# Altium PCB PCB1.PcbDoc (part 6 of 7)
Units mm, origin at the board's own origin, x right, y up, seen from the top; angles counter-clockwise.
Board outline 139.9 x 46.81 mm, 2 copper layers (Top Layer, Bottom Layer); 0 components, 100 nets, 100 pads, 0 vias.
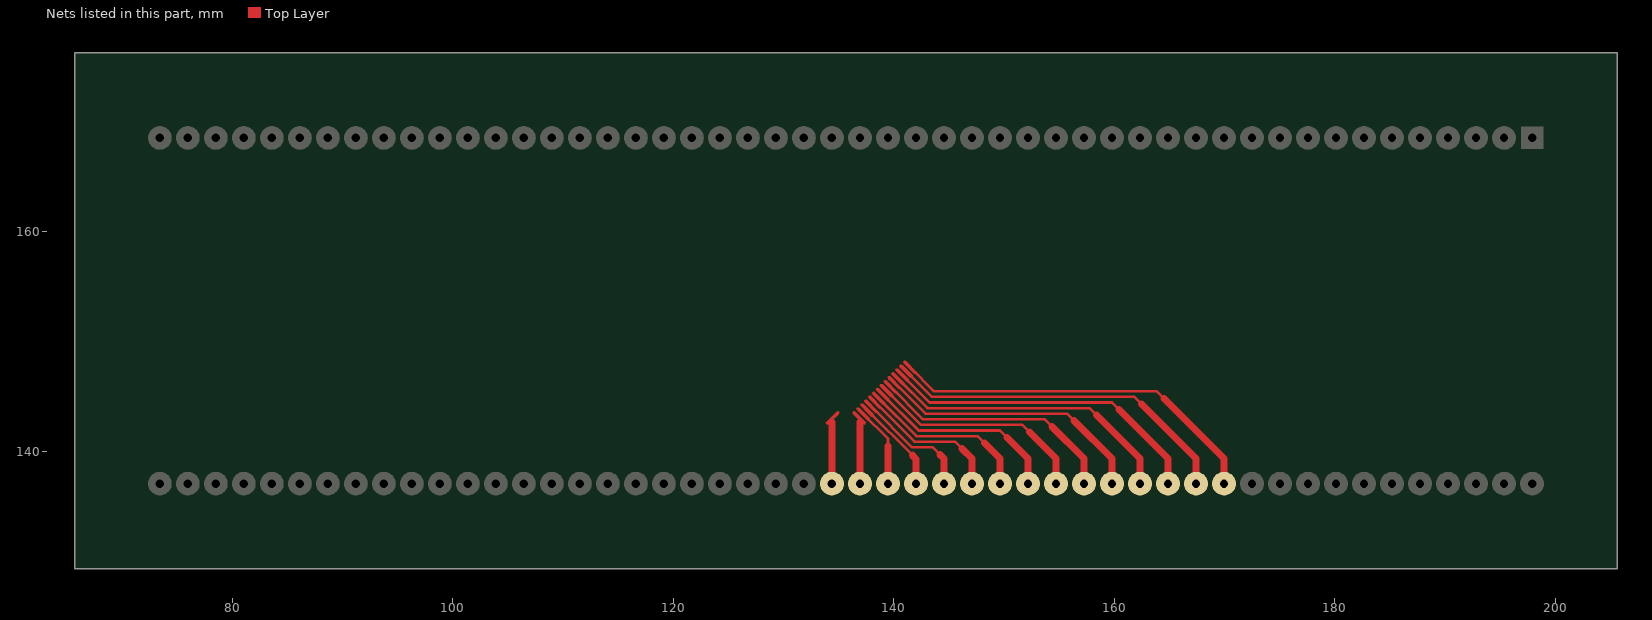
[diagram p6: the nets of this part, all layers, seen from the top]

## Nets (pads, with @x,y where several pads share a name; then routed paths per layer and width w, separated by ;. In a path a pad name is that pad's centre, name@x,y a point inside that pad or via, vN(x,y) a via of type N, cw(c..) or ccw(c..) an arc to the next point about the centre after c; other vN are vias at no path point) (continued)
$Net74: pad.1@134.387,137.086 | length 29.9
  Top Layer w0.03: 133.887,142.608 134.143,142.608 ; 133.887,142.623 134.158,142.623 ; 133.889,142.638 134.174,142.638 ; 133.892,142.592 134.128,142.592 ; 133.899,142.577 134.113,142.577 ; 133.91,142.562 134.098,142.562 ; 133.915,142.684 134.219,142.684 ; 133.922,142.547 134.082,142.547 ; 133.93,142.699 134.235,142.699 ; 133.938,142.532 134.067,142.532 ; 133.945,142.714 134.25,142.714 ; 133.96,142.516 134.049,142.516 ; 133.96,142.73 134.265,142.73 ; 133.976,142.745 134.28,142.745 ; 133.991,142.76 134.296,142.76 ; 134.006,142.775 134.311,142.775 ; 134.021,142.791 134.326,142.791 ; 134.037,142.806 134.341,142.806 ; 134.052,142.821 134.357,142.821 ; 134.067,142.836 134.372,142.836 ; 134.082,142.852 134.387,142.852 ; 134.098,142.867 134.402,142.867 ; 134.113,142.882 134.418,142.882 ; 134.128,142.897 134.433,142.897 ; 134.143,142.913 134.448,142.913 ; 134.158,142.928 134.463,142.928 ; 134.174,142.943 134.479,142.943 ; 134.189,142.653 133.892,142.653 ; 134.189,142.958 134.494,142.958 ; 134.204,142.669 133.899,142.669 ; 134.204,142.973 134.509,142.973 ; 134.219,142.989 134.527,142.989 ; 134.235,143.004 134.542,143.004 ; 134.25,143.019 134.557,143.019 ; 134.265,143.034 134.573,143.034 ; 134.28,143.05 134.588,143.05 ; 134.296,143.065 134.603,143.065 ; 134.311,143.08 134.618,143.08 ; 134.326,143.095 134.633,143.095 ; 134.341,143.111 134.649,143.111 ; 134.357,143.126 134.664,143.126 ; 134.372,143.141 134.679,143.141 ; 134.39,143.156 134.694,143.156 ; 134.405,143.172 134.71,143.172 ; 134.42,143.187 134.725,143.187 ; 134.435,143.202 134.74,143.202 ; 134.451,143.217 134.755,143.217 ; 134.466,143.233 134.771,143.233 ; 134.481,143.248 134.786,143.248 ; 134.496,143.263 134.801,143.263 ; 134.512,143.278 134.816,143.278 ; 134.527,143.294 134.832,143.294 ; 134.542,143.309 134.847,143.309 ; 134.557,143.324 134.862,143.324 ; 134.573,143.339 134.877,143.339 ; 134.588,143.354 134.893,143.354 ; 134.603,143.37 134.908,143.37 ; 134.618,143.385 134.923,143.385 ; 134.633,143.4 134.938,143.4 ; 134.649,143.415 134.954,143.415 ; 134.664,143.431 134.969,143.431 ; 134.679,143.446 134.984,143.446 ; 134.694,143.461 134.999,143.461 ; 134.71,143.476 135.009,143.476 ; 134.725,143.492 135.017,143.492 ; 134.74,143.507 135.02,143.507 ; 134.755,143.522 135.022,143.522 ; 134.771,143.537 135.02,143.537 ; 134.786,143.553 135.014,143.553 ; 134.801,143.568 135.004,143.568 ; 134.816,143.583 134.994,143.583 ; 134.832,143.598 134.979,143.598 ; 134.847,143.614 134.964,143.614 ; 134.867,143.629 134.941,143.629 ; 133.892,142.653 133.899,142.669 ; 133.892,142.653 133.884,142.62 133.887,142.603 133.892,142.587 133.912,142.557 133.94,142.529 133.971,142.509 133.986,142.504 134.004,142.501 134.037,142.509 134.049,142.516 ; 133.899,142.669 133.91,142.681 134.857,143.624 134.87,143.631 134.903,143.639 134.92,143.636 134.936,143.631 134.966,143.611 134.994,143.583 ; 134.049,142.516 134.997,143.459 135.007,143.471 135.014,143.487 135.022,143.52 135.02,143.537 ; 134.994,143.583 135.014,143.553 ; 135.014,143.553 135.02,143.537
  Top Layer w0.203: 134.387,142.674 134.387,143.001 134.453,143.07
  Top Layer w0.635: pad.1@134.387,137.086 134.387,142.674
$Net75: pad.1@136.927,137.086 | length 29.9
  Top Layer w0.03: 136.292,143.522 136.561,143.522 ; 136.295,143.507 136.577,143.507 ; 136.297,143.492 136.592,143.492 ; 136.305,143.476 136.607,143.476 ; 136.307,143.568 136.516,143.568 ; 136.317,143.461 136.622,143.461 ; 136.333,143.446 136.638,143.446 ; 136.333,143.598 136.485,143.598 ; 136.348,143.431 136.653,143.431 ; 136.351,143.614 136.47,143.614 ; 136.363,143.415 136.668,143.415 ; 136.373,143.629 136.447,143.629 ; 136.378,143.4 136.683,143.4 ; 136.394,143.385 136.698,143.385 ; 136.409,143.37 136.714,143.37 ; 136.424,143.354 136.729,143.354 ; 136.439,143.339 136.744,143.339 ; 136.455,143.324 136.759,143.324 ; 136.47,143.309 136.775,143.309 ; 136.485,143.294 136.79,143.294 ; 136.5,143.278 136.805,143.278 ; 136.5,143.583 136.317,143.583 ; 136.516,143.263 136.82,143.263 ; 136.531,143.248 136.836,143.248 ; 136.531,143.553 136.297,143.553 ; 136.546,143.233 136.851,143.233 ; 136.546,143.537 136.292,143.537 ; 136.561,143.217 136.866,143.217 ; 136.577,143.202 136.881,143.202 ; 136.592,143.187 136.897,143.187 ; 136.607,143.172 136.912,143.172 ; 136.622,143.156 136.927,143.156 ; 136.638,143.141 136.942,143.141 ; 136.653,143.126 136.955,143.126 ; 136.668,143.111 136.97,143.111 ; 136.683,143.095 136.986,143.095 ; 136.698,143.08 137.001,143.08 ; 136.714,143.065 137.016,143.065 ; 136.729,143.05 137.031,143.05 ; 136.744,143.034 137.046,143.034 ; 136.759,143.019 137.062,143.019 ; 136.775,143.004 137.077,143.004 ; 136.787,142.989 137.092,142.989 ; 136.803,142.973 137.107,142.973 ; 136.818,142.958 137.123,142.958 ; 136.833,142.943 137.138,142.943 ; 136.848,142.928 137.153,142.928 ; 136.864,142.913 137.168,142.913 ; 136.879,142.897 137.184,142.897 ; 136.894,142.882 137.199,142.882 ; 136.909,142.867 137.214,142.867 ; 136.925,142.852 137.229,142.852 ; 136.94,142.836 137.245,142.836 ; 136.955,142.821 137.26,142.821 ; 136.97,142.806 137.275,142.806 ; 136.986,142.791 137.29,142.791 ; 137.001,142.775 137.306,142.775 ; 137.016,142.76 137.321,142.76 ; 137.031,142.745 137.336,142.745 ; 137.046,142.73 137.351,142.73 ; 137.062,142.714 137.367,142.714 ; 137.077,142.699 137.382,142.699 ; 137.092,142.684 137.397,142.684 ; 137.107,142.669 137.412,142.669 ; 137.123,142.653 137.42,142.653 ; 137.138,142.638 137.425,142.638 ; 137.153,142.623 137.427,142.623 ; 137.168,142.608 137.427,142.608 ; 137.184,142.592 137.422,142.592 ; 137.199,142.577 137.415,142.577 ; 137.214,142.562 137.405,142.562 ; 137.229,142.547 137.389,142.547 ; 137.245,142.532 137.374,142.532 ; 137.354,142.516 137.26,142.516 ; 136.292,143.537 136.297,143.553 ; 136.292,143.537 136.29,143.52 136.297,143.487 136.305,143.474 137.247,142.526 137.26,142.516 ; 136.297,143.553 136.317,143.583 ; 136.317,143.583 136.345,143.611 136.376,143.631 136.391,143.636 136.409,143.639 136.442,143.631 136.457,143.624 136.47,143.614 ; 136.47,143.614 137.412,142.666 137.42,142.653 ; 137.26,142.516 137.275,142.509 137.308,142.501 137.326,142.504 137.341,142.509 137.372,142.529 137.4,142.557 137.42,142.587 137.425,142.603 137.427,142.62 137.42,142.653
  Top Layer w0.203: 136.859,143.07 136.927,143.001 136.927,142.674
  Top Layer w0.635: pad.1@136.927,137.086 136.927,142.674
$Net76: pad.1@139.467,137.086 | length 31.2
  Top Layer w0.03: 136.645,143.875 136.914,143.875 ; 136.648,143.86 136.93,143.86 ; 136.65,143.845 136.945,143.845 ; 136.658,143.829 136.96,143.829 ; 136.66,143.921 136.869,143.921 ; 136.671,143.814 136.975,143.814 ; 136.686,143.799 136.991,143.799 ; 136.686,143.951 136.838,143.951 ; 136.701,143.784 137.006,143.784 ; 136.704,143.967 136.823,143.967 ; 136.716,143.768 137.021,143.768 ; 136.726,143.982 136.8,143.982 ; 136.732,143.753 137.036,143.753 ; 136.747,143.738 137.052,143.738 ; 136.762,143.723 137.067,143.723 ; 136.777,143.708 137.082,143.708 ; 136.792,143.692 137.097,143.692 ; 136.808,143.677 137.113,143.677 ; 136.823,143.662 137.128,143.662 ; 136.838,143.647 137.143,143.647 ; 136.853,143.631 137.158,143.631 ; 136.853,143.936 136.671,143.936 ; 136.869,143.616 137.173,143.616 ; 136.884,143.601 137.189,143.601 ; 136.884,143.906 136.65,143.906 ; 136.899,143.586 137.204,143.586 ; 136.899,143.89 136.645,143.89 ; 136.914,143.57 137.219,143.57 ; 136.93,143.555 137.234,143.555 ; 136.945,143.54 137.25,143.54 ; 136.96,143.525 137.265,143.525 ; 136.975,143.509 137.28,143.509 ; 136.991,143.494 137.295,143.494 ; 137.006,143.479 137.308,143.479 ; 137.021,143.464 137.323,143.464 ; 137.036,143.448 137.339,143.448 ; 137.052,143.433 137.354,143.433 ; 137.067,143.418 137.369,143.418 ; 137.082,143.403 137.384,143.403 ; 137.097,143.387 137.4,143.387 ; 137.113,143.372 137.415,143.372 ; 137.128,143.357 137.43,143.357 ; 137.14,143.342 137.445,143.342 ; 137.156,143.327 137.46,143.327 ; 137.171,143.311 137.476,143.311 ; 137.186,143.296 137.491,143.296 ; 137.201,143.281 137.506,143.281 ; 137.217,143.266 137.521,143.266 ; 137.232,143.25 137.537,143.25 ; 137.247,143.235 137.552,143.235 ; 137.262,143.22 137.567,143.22 ; 137.278,143.205 137.582,143.205 ; 137.293,143.189 137.598,143.189 ; 137.308,143.174 137.613,143.174 ; 137.323,143.159 137.628,143.159 ; 137.339,143.144 137.643,143.144 ; 137.354,143.128 137.659,143.128 ; 137.369,143.113 137.674,143.113 ; 137.384,143.098 137.689,143.098 ; 137.4,143.083 137.704,143.083 ; 137.415,143.067 137.72,143.067 ; 137.43,143.052 137.735,143.052 ; 137.445,143.037 137.75,143.037 ; 137.46,143.022 137.765,143.022 ; 137.476,143.006 137.773,143.006 ; 137.491,142.991 137.778,142.991 ; 137.506,142.976 137.781,142.976 ; 137.521,142.961 137.781,142.961 ; 137.537,142.946 137.775,142.946 ; 137.552,142.93 137.768,142.93 ; 137.567,142.915 137.758,142.915 ; 137.582,142.9 137.742,142.9 ; 137.598,142.885 137.727,142.885 ; 137.707,142.869 137.613,142.869 ; 136.645,143.89 136.65,143.906 ; 136.645,143.89 136.643,143.873 136.65,143.84 136.658,143.827 137.6,142.879 137.613,142.869 ; 136.65,143.906 136.671,143.936 ; 136.671,143.936 136.698,143.964 136.729,143.984 136.744,143.989 136.762,143.992 136.795,143.984 136.81,143.977 136.823,143.967 ; 136.823,143.967 137.765,143.019 137.773,143.006 ; 137.613,142.869 137.628,142.862 137.661,142.854 137.679,142.857 137.694,142.862 137.725,142.882 137.753,142.91 137.773,142.94 137.778,142.956 137.781,142.973 137.773,143.006
  Top Layer w0.241: 137.212,143.423 139.467,141.168 139.467,140.515
  Top Layer w0.635: pad.1@139.467,137.086 139.467,140.515
$Net77: pad.1@142.007,137.086 | length 32.4
  Top Layer w0.03: 136.998,144.228 137.267,144.228 ; 137.001,144.213 137.283,144.213 ; 137.003,144.198 137.298,144.198 ; 137.011,144.183 137.313,144.183 ; 137.013,144.274 137.222,144.274 ; 137.024,144.167 137.328,144.167 ; 137.039,144.152 137.344,144.152 ; 137.039,144.304 137.191,144.304 ; 137.054,144.137 137.359,144.137 ; 137.057,144.32 137.176,144.32 ; 137.069,144.122 137.374,144.122 ; 137.079,144.335 137.153,144.335 ; 137.085,144.106 137.389,144.106 ; 137.1,144.091 137.405,144.091 ; 137.115,144.076 137.42,144.076 ; 137.13,144.061 137.435,144.061 ; 137.146,144.045 137.45,144.045 ; 137.161,144.03 137.466,144.03 ; 137.176,144.015 137.481,144.015 ; 137.191,144 137.496,144 ; 137.206,143.984 137.511,143.984 ; 137.206,144.289 137.024,144.289 ; 137.222,143.969 137.527,143.969 ; 137.237,143.954 137.542,143.954 ; 137.237,144.259 137.003,144.259 ; 137.252,143.939 137.557,143.939 ; 137.252,144.243 136.998,144.243 ; 137.267,143.923 137.572,143.923 ; 137.283,143.908 137.587,143.908 ; 137.298,143.893 137.603,143.893 ; 137.313,143.878 137.618,143.878 ; 137.328,143.862 137.633,143.862 ; 137.344,143.847 137.648,143.847 ; 137.359,143.832 137.661,143.832 ; 137.374,143.817 137.676,143.817 ; 137.389,143.802 137.692,143.802 ; 137.405,143.786 137.707,143.786 ; 137.42,143.771 137.722,143.771 ; 137.435,143.756 137.737,143.756 ; 137.45,143.741 137.753,143.741 ; 137.466,143.725 137.768,143.725 ; 137.481,143.71 137.783,143.71 ; 137.494,143.695 137.798,143.695 ; 137.509,143.68 137.814,143.68 ; 137.524,143.664 137.829,143.664 ; 137.539,143.649 137.844,143.649 ; 137.554,143.634 137.859,143.634 ; 137.57,143.619 137.875,143.619 ; 137.585,143.603 137.89,143.603 ; 137.6,143.588 137.905,143.588 ; 137.615,143.573 137.92,143.573 ; 137.631,143.558 137.935,143.558 ; 137.646,143.542 137.951,143.542 ; 137.661,143.527 137.966,143.527 ; 137.676,143.512 137.981,143.512 ; 137.692,143.497 137.996,143.497 ; 137.707,143.481 138.012,143.481 ; 137.722,143.466 138.027,143.466 ; 137.737,143.451 138.042,143.451 ; 137.753,143.436 138.057,143.436 ; 137.768,143.421 138.073,143.421 ; 137.783,143.405 138.088,143.405 ; 137.798,143.39 138.103,143.39 ; 137.814,143.375 138.118,143.375 ; 137.829,143.36 138.126,143.36 ; 137.844,143.344 138.131,143.344 ; 137.859,143.329 138.134,143.329 ; 137.875,143.314 138.134,143.314 ; 137.89,143.299 138.129,143.299 ; 137.905,143.283 138.121,143.283 ; 137.92,143.268 138.111,143.268 ; 137.935,143.253 138.095,143.253 ; 137.951,143.238 138.08,143.238 ; 138.06,143.222 137.966,143.222 ; 136.998,144.243 137.003,144.259 ; 136.998,144.243 136.996,144.226 137.003,144.193 137.011,144.18 137.953,143.233 137.966,143.222 ; 137.003,144.259 137.024,144.289 ; 137.024,144.289 137.052,144.317 137.082,144.337 137.097,144.343 137.115,144.345 137.148,144.337 137.163,144.33 137.176,144.32 ; 137.176,144.32 138.118,143.372 138.126,143.36 ; 137.966,143.222 137.981,143.215 138.014,143.207 138.032,143.21 138.047,143.215 138.078,143.235 138.106,143.263 138.126,143.294 138.131,143.309 138.134,143.327 138.126,143.36
  Top Layer w0.241: 137.565,143.776 141.672,139.671
  Top Layer w0.635: 141.672,139.671 142.007,139.336 pad.1@142.007,137.086
$Net78: pad.1@144.547,137.086 | length 34.8
  Top Layer w0.03: 137.351,144.581 137.621,144.581 ; 137.354,144.566 137.636,144.566 ; 137.356,144.551 137.651,144.551 ; 137.364,144.536 137.666,144.536 ; 137.367,144.627 137.575,144.627 ; 137.377,144.52 137.681,144.52 ; 137.392,144.505 137.697,144.505 ; 137.392,144.657 137.544,144.657 ; 137.407,144.49 137.712,144.49 ; 137.41,144.673 137.529,144.673 ; 137.422,144.475 137.727,144.475 ; 137.433,144.688 137.506,144.688 ; 137.438,144.459 137.742,144.459 ; 137.453,144.444 137.758,144.444 ; 137.468,144.429 137.773,144.429 ; 137.483,144.414 137.788,144.414 ; 137.499,144.398 137.803,144.398 ; 137.514,144.383 137.819,144.383 ; 137.529,144.368 137.834,144.368 ; 137.544,144.353 137.849,144.353 ; 137.56,144.337 137.864,144.337 ; 137.56,144.642 137.377,144.642 ; 137.575,144.322 137.88,144.322 ; 137.59,144.307 137.895,144.307 ; 137.59,144.612 137.356,144.612 ; 137.605,144.292 137.91,144.292 ; 137.605,144.597 137.351,144.597 ; 137.621,144.276 137.925,144.276 ; 137.636,144.261 137.941,144.261 ; 137.651,144.246 137.956,144.246 ; 137.666,144.231 137.971,144.231 ; 137.681,144.216 137.986,144.216 ; 137.697,144.2 138.002,144.2 ; 137.712,144.185 138.014,144.185 ; 137.727,144.17 138.029,144.17 ; 137.742,144.155 138.045,144.155 ; 137.758,144.139 138.06,144.139 ; 137.773,144.124 138.075,144.124 ; 137.788,144.109 138.09,144.109 ; 137.803,144.094 138.106,144.094 ; 137.819,144.078 138.121,144.078 ; 137.834,144.063 138.136,144.063 ; 137.847,144.048 138.151,144.048 ; 137.862,144.033 138.167,144.033 ; 137.877,144.017 138.182,144.017 ; 137.892,144.002 138.197,144.002 ; 137.908,143.987 138.212,143.987 ; 137.923,143.972 138.228,143.972 ; 137.938,143.956 138.243,143.956 ; 137.953,143.941 138.258,143.941 ; 137.968,143.926 138.273,143.926 ; 137.984,143.911 138.289,143.911 ; 137.999,143.895 138.304,143.895 ; 138.014,143.88 138.319,143.88 ; 138.029,143.865 138.334,143.865 ; 138.045,143.85 138.349,143.85 ; 138.06,143.835 138.365,143.835 ; 138.075,143.819 138.38,143.819 ; 138.09,143.804 138.395,143.804 ; 138.106,143.789 138.41,143.789 ; 138.121,143.774 138.426,143.774 ; 138.136,143.758 138.441,143.758 ; 138.151,143.743 138.456,143.743 ; 138.167,143.728 138.471,143.728 ; 138.182,143.713 138.479,143.713 ; 138.197,143.697 138.484,143.697 ; 138.212,143.682 138.487,143.682 ; 138.228,143.667 138.487,143.667 ; 138.243,143.652 138.482,143.652 ; 138.258,143.636 138.474,143.636 ; 138.273,143.621 138.464,143.621 ; 138.289,143.606 138.449,143.606 ; 138.304,143.591 138.433,143.591 ; 138.413,143.575 138.319,143.575 ; 137.351,144.597 137.356,144.612 ; 137.351,144.597 137.349,144.579 137.356,144.546 137.364,144.533 138.306,143.586 138.319,143.575 ; 137.356,144.612 137.377,144.642 ; 137.377,144.642 137.405,144.67 137.435,144.691 137.45,144.696 137.468,144.698 137.501,144.691 137.516,144.683 137.529,144.673 ; 137.529,144.673 138.471,143.725 138.479,143.713 ; 138.319,143.575 138.334,143.568 138.367,143.56 138.385,143.563 138.4,143.568 138.431,143.588 138.459,143.616 138.479,143.647 138.484,143.662 138.487,143.68 138.479,143.713
  Top Layer w0.241: 137.918,144.129 141.662,140.388 143.531,140.388 144.166,139.753
  Top Layer w0.635: 144.166,139.753 144.547,139.372 pad.1@144.547,137.086
$Net79: pad.1@147.087,137.086 | length 37.1
  Top Layer w0.03: 137.707,144.937 137.976,144.937 ; 137.709,144.922 137.991,144.922 ; 137.712,144.906 138.007,144.906 ; 137.72,144.891 138.022,144.891 ; 137.722,144.983 137.93,144.983 ; 137.732,144.876 138.037,144.876 ; 137.748,144.861 138.052,144.861 ; 137.748,145.013 137.9,145.013 ; 137.763,144.845 138.068,144.845 ; 137.765,145.028 137.885,145.028 ; 137.778,144.83 138.083,144.83 ; 137.788,145.044 137.862,145.044 ; 137.793,144.815 138.098,144.815 ; 137.808,144.8 138.113,144.8 ; 137.824,144.784 138.129,144.784 ; 137.839,144.769 138.144,144.769 ; 137.854,144.754 138.159,144.754 ; 137.869,144.739 138.174,144.739 ; 137.885,144.724 138.189,144.724 ; 137.9,144.708 138.205,144.708 ; 137.915,144.693 138.22,144.693 ; 137.915,144.998 137.732,144.998 ; 137.93,144.678 138.235,144.678 ; 137.946,144.663 138.25,144.663 ; 137.946,144.967 137.712,144.967 ; 137.961,144.647 138.266,144.647 ; 137.961,144.952 137.707,144.952 ; 137.976,144.632 138.281,144.632 ; 137.991,144.617 138.296,144.617 ; 138.007,144.602 138.311,144.602 ; 138.022,144.586 138.327,144.586 ; 138.037,144.571 138.342,144.571 ; 138.052,144.556 138.357,144.556 ; 138.068,144.541 138.37,144.541 ; 138.083,144.525 138.385,144.525 ; 138.098,144.51 138.4,144.51 ; 138.113,144.495 138.416,144.495 ; 138.129,144.48 138.431,144.48 ; 138.144,144.464 138.446,144.464 ; 138.159,144.449 138.461,144.449 ; 138.174,144.434 138.476,144.434 ; 138.189,144.419 138.492,144.419 ; 138.202,144.403 138.507,144.403 ; 138.217,144.388 138.522,144.388 ; 138.233,144.373 138.537,144.373 ; 138.248,144.358 138.553,144.358 ; 138.263,144.343 138.568,144.343 ; 138.278,144.327 138.583,144.327 ; 138.294,144.312 138.598,144.312 ; 138.309,144.297 138.614,144.297 ; 138.324,144.282 138.629,144.282 ; 138.339,144.266 138.644,144.266 ; 138.355,144.251 138.659,144.251 ; 138.37,144.236 138.675,144.236 ; 138.385,144.221 138.69,144.221 ; 138.4,144.205 138.705,144.205 ; 138.416,144.19 138.72,144.19 ; 138.431,144.175 138.736,144.175 ; 138.446,144.16 138.751,144.16 ; 138.461,144.144 138.766,144.144 ; 138.476,144.129 138.781,144.129 ; 138.492,144.114 138.797,144.114 ; 138.507,144.099 138.812,144.099 ; 138.522,144.083 138.827,144.083 ; 138.537,144.068 138.835,144.068 ; 138.553,144.053 138.84,144.053 ; 138.568,144.038 138.842,144.038 ; 138.583,144.022 138.842,144.022 ; 138.598,144.007 138.837,144.007 ; 138.614,143.992 138.83,143.992 ; 138.629,143.977 138.819,143.977 ; 138.644,143.962 138.804,143.962 ; 138.659,143.946 138.789,143.946 ; 138.769,143.931 138.675,143.931 ; 137.707,144.952 137.712,144.967 ; 137.707,144.952 137.704,144.934 137.712,144.901 137.72,144.889 138.662,143.941 138.675,143.931 ; 137.712,144.967 137.732,144.998 ; 137.732,144.998 137.76,145.026 137.791,145.046 137.806,145.051 137.824,145.054 137.857,145.046 137.872,145.038 137.885,145.028 ; 137.885,145.028 138.827,144.081 138.835,144.068 ; 138.675,143.931 138.69,143.923 138.723,143.916 138.741,143.918 138.756,143.923 138.786,143.944 138.814,143.972 138.835,144.002 138.84,144.017 138.842,144.035 138.835,144.068
  Top Layer w0.241: 138.273,144.485 141.86,140.896 145.563,140.896 146.198,140.261
  Top Layer w0.635: 146.198,140.261 147.087,139.372 pad.1@147.087,137.086
$Net80: pad.1@149.627,137.086 | length 39.5
  Top Layer w0.03: 138.06,145.29 138.329,145.29 ; 138.062,145.275 138.344,145.275 ; 138.065,145.259 138.36,145.259 ; 138.073,145.244 138.375,145.244 ; 138.075,145.336 138.283,145.336 ; 138.085,145.229 138.39,145.229 ; 138.101,145.214 138.405,145.214 ; 138.101,145.366 138.253,145.366 ; 138.116,145.199 138.421,145.199 ; 138.118,145.381 138.238,145.381 ; 138.131,145.183 138.436,145.183 ; 138.141,145.397 138.215,145.397 ; 138.146,145.168 138.451,145.168 ; 138.162,145.153 138.466,145.153 ; 138.177,145.138 138.482,145.138 ; 138.192,145.122 138.497,145.122 ; 138.207,145.107 138.512,145.107 ; 138.222,145.092 138.527,145.092 ; 138.238,145.077 138.543,145.077 ; 138.253,145.061 138.558,145.061 ; 138.268,145.046 138.573,145.046 ; 138.268,145.351 138.085,145.351 ; 138.283,145.031 138.588,145.031 ; 138.299,145.016 138.603,145.016 ; 138.299,145.32 138.065,145.32 ; 138.314,145 138.619,145 ; 138.314,145.305 138.06,145.305 ; 138.329,144.985 138.634,144.985 ; 138.344,144.97 138.649,144.97 ; 138.36,144.955 138.664,144.955 ; 138.375,144.939 138.68,144.939 ; 138.39,144.924 138.695,144.924 ; 138.405,144.909 138.71,144.909 ; 138.421,144.894 138.723,144.894 ; 138.436,144.878 138.738,144.878 ; 138.451,144.863 138.753,144.863 ; 138.466,144.848 138.769,144.848 ; 138.482,144.833 138.784,144.833 ; 138.497,144.818 138.799,144.818 ; 138.512,144.802 138.814,144.802 ; 138.527,144.787 138.83,144.787 ; 138.543,144.772 138.845,144.772 ; 138.555,144.757 138.86,144.757 ; 138.57,144.741 138.875,144.741 ; 138.586,144.726 138.891,144.726 ; 138.601,144.711 138.906,144.711 ; 138.616,144.696 138.921,144.696 ; 138.631,144.68 138.936,144.68 ; 138.647,144.665 138.951,144.665 ; 138.662,144.65 138.967,144.65 ; 138.677,144.635 138.982,144.635 ; 138.692,144.619 138.997,144.619 ; 138.708,144.604 139.012,144.604 ; 138.723,144.589 139.028,144.589 ; 138.738,144.574 139.043,144.574 ; 138.753,144.558 139.058,144.558 ; 138.769,144.543 139.073,144.543 ; 138.784,144.528 139.089,144.528 ; 138.799,144.513 139.104,144.513 ; 138.814,144.497 139.119,144.497 ; 138.83,144.482 139.134,144.482 ; 138.845,144.467 139.15,144.467 ; 138.86,144.452 139.165,144.452 ; 138.875,144.437 139.18,144.437 ; 138.891,144.421 139.188,144.421 ; 138.906,144.406 139.193,144.406 ; 138.921,144.391 139.195,144.391 ; 138.936,144.376 139.195,144.376 ; 138.951,144.36 139.19,144.36 ; 138.967,144.345 139.183,144.345 ; 138.982,144.33 139.172,144.33 ; 138.997,144.315 139.157,144.315 ; 139.012,144.299 139.142,144.299 ; 139.122,144.284 139.028,144.284 ; 138.06,145.305 138.065,145.32 ; 138.06,145.305 138.057,145.287 138.065,145.254 138.073,145.242 139.015,144.294 139.028,144.284 ; 138.065,145.32 138.085,145.351 ; 138.085,145.351 138.113,145.379 138.144,145.399 138.159,145.404 138.177,145.407 138.21,145.399 138.225,145.392 138.238,145.381 ; 138.238,145.381 139.18,144.434 139.188,144.421 ; 139.028,144.284 139.043,144.276 139.076,144.269 139.094,144.271 139.109,144.276 139.139,144.297 139.167,144.325 139.188,144.355 139.193,144.37 139.195,144.388 139.188,144.421
  Top Layer w0.241: 138.626,144.838 142.06,141.404 147.595,141.404 148.23,140.769
  Top Layer w0.635: 148.23,140.769 149.627,139.372 pad.1@149.627,137.086
$Net81: pad.1@152.167,137.086 | length 41.8
  Top Layer w0.03: 138.413,145.643 138.682,145.643 ; 138.416,145.628 138.697,145.628 ; 138.418,145.613 138.713,145.613 ; 138.426,145.597 138.728,145.597 ; 138.428,145.689 138.637,145.689 ; 138.438,145.582 138.743,145.582 ; 138.454,145.567 138.758,145.567 ; 138.454,145.719 138.606,145.719 ; 138.469,145.552 138.774,145.552 ; 138.471,145.734 138.591,145.734 ; 138.484,145.536 138.789,145.536 ; 138.494,145.75 138.568,145.75 ; 138.499,145.521 138.804,145.521 ; 138.515,145.506 138.819,145.506 ; 138.53,145.491 138.835,145.491 ; 138.545,145.475 138.85,145.475 ; 138.56,145.46 138.865,145.46 ; 138.576,145.445 138.88,145.445 ; 138.591,145.43 138.896,145.43 ; 138.606,145.414 138.911,145.414 ; 138.621,145.399 138.926,145.399 ; 138.621,145.704 138.438,145.704 ; 138.637,145.384 138.941,145.384 ; 138.652,145.369 138.957,145.369 ; 138.652,145.673 138.418,145.673 ; 138.667,145.353 138.972,145.353 ; 138.667,145.658 138.413,145.658 ; 138.682,145.338 138.987,145.338 ; 138.697,145.323 139.002,145.323 ; 138.713,145.308 139.018,145.308 ; 138.728,145.292 139.033,145.292 ; 138.743,145.277 139.048,145.277 ; 138.758,145.262 139.063,145.262 ; 138.774,145.247 139.076,145.247 ; 138.789,145.232 139.091,145.232 ; 138.804,145.216 139.106,145.216 ; 138.819,145.201 139.122,145.201 ; 138.835,145.186 139.137,145.186 ; 138.85,145.171 139.152,145.171 ; 138.865,145.155 139.167,145.155 ; 138.88,145.14 139.183,145.14 ; 138.896,145.125 139.198,145.125 ; 138.908,145.11 139.213,145.11 ; 138.924,145.094 139.228,145.094 ; 138.939,145.079 139.244,145.079 ; 138.954,145.064 139.259,145.064 ; 138.969,145.049 139.274,145.049 ; 138.984,145.033 139.289,145.033 ; 139,145.018 139.305,145.018 ; 139.015,145.003 139.32,145.003 ; 139.03,144.988 139.335,144.988 ; 139.045,144.972 139.35,144.972 ; 139.061,144.957 139.365,144.957 ; 139.076,144.942 139.381,144.942 ; 139.091,144.927 139.396,144.927 ; 139.106,144.911 139.411,144.911 ; 139.122,144.896 139.426,144.896 ; 139.137,144.881 139.442,144.881 ; 139.152,144.866 139.457,144.866 ; 139.167,144.851 139.472,144.851 ; 139.183,144.835 139.487,144.835 ; 139.198,144.82 139.503,144.82 ; 139.213,144.805 139.518,144.805 ; 139.228,144.79 139.533,144.79 ; 139.244,144.774 139.541,144.774 ; 139.259,144.759 139.546,144.759 ; 139.274,144.744 139.548,144.744 ; 139.289,144.729 139.548,144.729 ; 139.305,144.713 139.543,144.713 ; 139.32,144.698 139.536,144.698 ; 139.335,144.683 139.526,144.683 ; 139.35,144.668 139.51,144.668 ; 139.365,144.652 139.495,144.652 ; 139.475,144.637 139.381,144.637 ; 138.413,145.658 138.418,145.673 ; 138.413,145.658 138.41,145.64 138.418,145.607 138.426,145.595 139.368,144.647 139.381,144.637 ; 138.418,145.673 138.438,145.704 ; 138.438,145.704 138.466,145.732 138.497,145.752 138.512,145.757 138.53,145.76 138.563,145.752 138.578,145.745 138.591,145.734 ; 138.591,145.734 139.533,144.787 139.541,144.774 ; 139.381,144.637 139.396,144.63 139.429,144.622 139.447,144.624 139.462,144.63 139.492,144.65 139.52,144.678 139.541,144.708 139.546,144.724 139.548,144.741 139.541,144.774
  Top Layer w0.241: 138.979,145.191 142.259,141.912 149.627,141.912 150.262,141.277
  Top Layer w0.635: 150.262,141.277 152.167,139.372 pad.1@152.167,137.086
$Net82: pad.1@154.707,137.086 | length 44.1
  Top Layer w0.03: 138.766,145.996 139.035,145.996 ; 138.769,145.981 139.051,145.981 ; 138.771,145.966 139.066,145.966 ; 138.779,145.95 139.081,145.95 ; 138.781,146.042 138.99,146.042 ; 138.791,145.935 139.096,145.935 ; 138.807,145.92 139.111,145.92 ; 138.807,146.072 138.959,146.072 ; 138.822,145.905 139.127,145.905 ; 138.824,146.088 138.944,146.088 ; 138.837,145.889 139.142,145.889 ; 138.847,146.103 138.921,146.103 ; 138.852,145.874 139.157,145.874 ; 138.868,145.859 139.172,145.859 ; 138.883,145.844 139.188,145.844 ; 138.898,145.828 139.203,145.828 ; 138.913,145.813 139.218,145.813 ; 138.929,145.798 139.233,145.798 ; 138.944,145.783 139.249,145.783 ; 138.959,145.767 139.264,145.767 ; 138.974,145.752 139.279,145.752 ; 138.974,146.057 138.791,146.057 ; 138.99,145.737 139.294,145.737 ; 139.005,145.722 139.31,145.722 ; 139.005,146.027 138.771,146.027 ; 139.02,145.707 139.325,145.707 ; 139.02,146.011 138.766,146.011 ; 139.035,145.691 139.34,145.691 ; 139.051,145.676 139.355,145.676 ; 139.066,145.661 139.371,145.661 ; 139.081,145.646 139.386,145.646 ; 139.096,145.63 139.401,145.63 ; 139.111,145.615 139.416,145.615 ; 139.127,145.6 139.429,145.6 ; 139.142,145.585 139.444,145.585 ; 139.157,145.569 139.459,145.569 ; 139.172,145.554 139.475,145.554 ; 139.188,145.539 139.49,145.539 ; 139.203,145.524 139.505,145.524 ; 139.218,145.508 139.52,145.508 ; 139.233,145.493 139.536,145.493 ; 139.249,145.478 139.551,145.478 ; 139.261,145.463 139.566,145.463 ; 139.277,145.447 139.581,145.447 ; 139.292,145.432 139.597,145.432 ; 139.307,145.417 139.612,145.417 ; 139.322,145.402 139.627,145.402 ; 139.338,145.386 139.642,145.386 ; 139.353,145.371 139.658,145.371 ; 139.368,145.356 139.673,145.356 ; 139.383,145.341 139.688,145.341 ; 139.399,145.326 139.703,145.326 ; 139.414,145.31 139.719,145.31 ; 139.429,145.295 139.734,145.295 ; 139.444,145.28 139.749,145.28 ; 139.459,145.265 139.764,145.265 ; 139.475,145.249 139.78,145.249 ; 139.49,145.234 139.795,145.234 ; 139.505,145.219 139.81,145.219 ; 139.52,145.204 139.825,145.204 ; 139.536,145.188 139.84,145.188 ; 139.551,145.173 139.856,145.173 ; 139.566,145.158 139.871,145.158 ; 139.581,145.143 139.886,145.143 ; 139.597,145.127 139.894,145.127 ; 139.612,145.112 139.899,145.112 ; 139.627,145.097 139.901,145.097 ; 139.642,145.082 139.901,145.082 ; 139.658,145.066 139.896,145.066 ; 139.673,145.051 139.889,145.051 ; 139.688,145.036 139.879,145.036 ; 139.703,145.021 139.863,145.021 ; 139.719,145.005 139.848,145.005 ; 139.828,144.99 139.734,144.99 ; 138.766,146.011 138.771,146.027 ; 138.766,146.011 138.764,145.994 138.771,145.961 138.779,145.948 139.721,145 139.734,144.99 ; 138.771,146.027 138.791,146.057 ; 138.791,146.057 138.819,146.085 138.85,146.105 138.865,146.11 138.883,146.113 138.916,146.105 138.931,146.098 138.944,146.088 ; 138.944,146.088 139.886,145.14 139.894,145.127 ; 139.734,144.99 139.749,144.983 139.782,144.975 139.8,144.978 139.815,144.983 139.846,145.003 139.873,145.031 139.894,145.061 139.899,145.077 139.901,145.094 139.894,145.127
  Top Layer w0.241: 139.332,145.544 142.459,142.42 151.659,142.42 152.294,141.785
  Top Layer w0.635: 152.294,141.785 154.707,139.372 pad.1@154.707,137.086
$Net83: pad.1@157.247,137.086 | length 46.5
  Top Layer w0.03: 139.119,146.349 139.388,146.349 ; 139.122,146.334 139.404,146.334 ; 139.124,146.319 139.419,146.319 ; 139.132,146.303 139.434,146.303 ; 139.134,146.395 139.343,146.395 ; 139.145,146.288 139.449,146.288 ; 139.16,146.273 139.465,146.273 ; 139.16,146.425 139.312,146.425 ; 139.175,146.258 139.48,146.258 ; 139.178,146.441 139.297,146.441 ; 139.19,146.242 139.495,146.242 ; 139.2,146.456 139.274,146.456 ; 139.205,146.227 139.51,146.227 ; 139.221,146.212 139.526,146.212 ; 139.236,146.197 139.541,146.197 ; 139.251,146.181 139.556,146.181 ; 139.266,146.166 139.571,146.166 ; 139.282,146.151 139.586,146.151 ; 139.297,146.136 139.602,146.136 ; 139.312,146.121 139.617,146.121 ; 139.327,146.105 139.632,146.105 ; 139.327,146.41 139.145,146.41 ; 139.343,146.09 139.647,146.09 ; 139.358,146.075 139.663,146.075 ; 139.358,146.38 139.124,146.38 ; 139.373,146.06 139.678,146.06 ; 139.373,146.364 139.119,146.364 ; 139.388,146.044 139.693,146.044 ; 139.404,146.029 139.708,146.029 ; 139.419,146.014 139.724,146.014 ; 139.434,145.999 139.739,145.999 ; 139.449,145.983 139.754,145.983 ; 139.465,145.968 139.769,145.968 ; 139.48,145.953 139.782,145.953 ; 139.495,145.938 139.797,145.938 ; 139.51,145.922 139.813,145.922 ; 139.526,145.907 139.828,145.907 ; 139.541,145.892 139.843,145.892 ; 139.556,145.877 139.858,145.877 ; 139.571,145.861 139.873,145.861 ; 139.586,145.846 139.889,145.846 ; 139.602,145.831 139.904,145.831 ; 139.614,145.816 139.919,145.816 ; 139.63,145.8 139.934,145.8 ; 139.645,145.785 139.95,145.785 ; 139.66,145.77 139.965,145.77 ; 139.675,145.755 139.98,145.755 ; 139.691,145.74 139.995,145.74 ; 139.706,145.724 140.011,145.724 ; 139.721,145.709 140.026,145.709 ; 139.736,145.694 140.041,145.694 ; 139.752,145.679 140.056,145.679 ; 139.767,145.663 140.072,145.663 ; 139.782,145.648 140.087,145.648 ; 139.797,145.633 140.102,145.633 ; 139.813,145.618 140.117,145.618 ; 139.828,145.602 140.133,145.602 ; 139.843,145.587 140.148,145.587 ; 139.858,145.572 140.163,145.572 ; 139.873,145.557 140.178,145.557 ; 139.889,145.541 140.194,145.541 ; 139.904,145.526 140.209,145.526 ; 139.919,145.511 140.224,145.511 ; 139.934,145.496 140.239,145.496 ; 139.95,145.48 140.247,145.48 ; 139.965,145.465 140.252,145.465 ; 139.98,145.45 140.254,145.45 ; 139.995,145.435 140.254,145.435 ; 140.011,145.419 140.249,145.419 ; 140.026,145.404 140.242,145.404 ; 140.041,145.389 140.232,145.389 ; 140.056,145.374 140.216,145.374 ; 140.072,145.359 140.201,145.359 ; 140.181,145.343 140.087,145.343 ; 139.119,146.364 139.124,146.38 ; 139.119,146.364 139.117,146.347 139.124,146.314 139.132,146.301 140.074,145.353 140.087,145.343 ; 139.124,146.38 139.145,146.41 ; 139.145,146.41 139.172,146.438 139.203,146.458 139.218,146.463 139.236,146.466 139.269,146.458 139.284,146.451 139.297,146.441 ; 139.297,146.441 140.239,145.493 140.247,145.48 ; 140.087,145.343 140.102,145.336 140.135,145.328 140.153,145.331 140.168,145.336 140.199,145.356 140.227,145.384 140.247,145.414 140.252,145.43 140.254,145.447 140.247,145.48
  Top Layer w0.241: 139.686,145.897 142.657,142.928 153.691,142.928 154.326,142.293
  Top Layer w0.635: 154.326,142.293 157.247,139.372 pad.1@157.247,137.086
$Net84: pad.1@159.787,137.086 | length 48.8
  Top Layer w0.03: 139.475,146.705 139.744,146.705 ; 139.477,146.689 139.759,146.689 ; 139.48,146.674 139.774,146.674 ; 139.487,146.659 139.79,146.659 ; 139.49,146.75 139.698,146.75 ; 139.5,146.644 139.805,146.644 ; 139.515,146.629 139.82,146.629 ; 139.515,146.781 139.668,146.781 ; 139.531,146.613 139.835,146.613 ; 139.533,146.796 139.653,146.796 ; 139.546,146.598 139.851,146.598 ; 139.556,146.811 139.63,146.811 ; 139.561,146.583 139.866,146.583 ; 139.576,146.568 139.881,146.568 ; 139.592,146.552 139.896,146.552 ; 139.607,146.537 139.912,146.537 ; 139.622,146.522 139.927,146.522 ; 139.637,146.507 139.942,146.507 ; 139.653,146.491 139.957,146.491 ; 139.668,146.476 139.973,146.476 ; 139.683,146.461 139.988,146.461 ; 139.683,146.766 139.5,146.766 ; 139.698,146.446 140.003,146.446 ; 139.713,146.43 140.018,146.43 ; 139.713,146.735 139.48,146.735 ; 139.729,146.415 140.034,146.415 ; 139.729,146.72 139.475,146.72 ; 139.744,146.4 140.049,146.4 ; 139.759,146.385 140.064,146.385 ; 139.774,146.369 140.079,146.369 ; 139.79,146.354 140.094,146.354 ; 139.805,146.339 140.11,146.339 ; 139.82,146.324 140.125,146.324 ; 139.835,146.308 140.138,146.308 ; 139.851,146.293 140.153,146.293 ; 139.866,146.278 140.168,146.278 ; 139.881,146.263 140.183,146.263 ; 139.896,146.248 140.199,146.248 ; 139.912,146.232 140.214,146.232 ; 139.927,146.217 140.229,146.217 ; 139.942,146.202 140.244,146.202 ; 139.957,146.187 140.26,146.187 ; 139.97,146.171 140.275,146.171 ; 139.985,146.156 140.29,146.156 ; 140,146.141 140.305,146.141 ; 140.016,146.126 140.321,146.126 ; 140.031,146.11 140.336,146.11 ; 140.046,146.095 140.351,146.095 ; 140.061,146.08 140.366,146.08 ; 140.077,146.065 140.381,146.065 ; 140.092,146.049 140.397,146.049 ; 140.107,146.034 140.412,146.034 ; 140.122,146.019 140.427,146.019 ; 140.138,146.004 140.442,146.004 ; 140.153,145.988 140.458,145.988 ; 140.168,145.973 140.473,145.973 ; 140.183,145.958 140.488,145.958 ; 140.199,145.943 140.503,145.943 ; 140.214,145.927 140.519,145.927 ; 140.229,145.912 140.534,145.912 ; 140.244,145.897 140.549,145.897 ; 140.26,145.882 140.564,145.882 ; 140.275,145.867 140.58,145.867 ; 140.29,145.851 140.595,145.851 ; 140.305,145.836 140.602,145.836 ; 140.321,145.821 140.608,145.821 ; 140.336,145.806 140.61,145.806 ; 140.351,145.79 140.61,145.79 ; 140.366,145.775 140.605,145.775 ; 140.381,145.76 140.597,145.76 ; 140.397,145.745 140.587,145.745 ; 140.412,145.729 140.572,145.729 ; 140.427,145.714 140.557,145.714 ; 140.536,145.699 140.442,145.699 ; 139.475,146.72 139.48,146.735 ; 139.475,146.72 139.472,146.702 139.48,146.669 139.487,146.656 140.43,145.709 140.442,145.699 ; 139.48,146.735 139.5,146.766 ; 139.5,146.766 139.528,146.794 139.559,146.814 139.574,146.819 139.592,146.822 139.625,146.814 139.64,146.806 139.653,146.796 ; 139.653,146.796 140.595,145.849 140.602,145.836 ; 140.442,145.699 140.458,145.691 140.491,145.684 140.508,145.686 140.524,145.691 140.554,145.712 140.582,145.74 140.602,145.77 140.608,145.785 140.61,145.803 140.602,145.836
  Top Layer w0.241: 140.041,146.253 142.855,143.436 155.723,143.436 156.358,142.801
  Top Layer w0.635: 156.358,142.801 159.787,139.372 pad.1@159.787,137.086
$Net85: pad.1@162.327,137.086 | length 51.1
  Top Layer w0.03: 139.828,147.058 140.097,147.058 ; 139.83,147.043 140.112,147.043 ; 139.833,147.027 140.127,147.027 ; 139.84,147.012 140.143,147.012 ; 139.843,147.104 140.051,147.104 ; 139.853,146.997 140.158,146.997 ; 139.868,146.982 140.173,146.982 ; 139.868,147.134 140.021,147.134 ; 139.884,146.966 140.188,146.966 ; 139.886,147.149 140.006,147.149 ; 139.899,146.951 140.204,146.951 ; 139.909,147.164 139.983,147.164 ; 139.914,146.936 140.219,146.936 ; 139.929,146.921 140.234,146.921 ; 139.945,146.905 140.249,146.905 ; 139.96,146.89 140.265,146.89 ; 139.975,146.875 140.28,146.875 ; 139.99,146.86 140.295,146.86 ; 140.006,146.844 140.31,146.844 ; 140.021,146.829 140.326,146.829 ; 140.036,146.814 140.341,146.814 ; 140.036,147.119 139.853,147.119 ; 140.051,146.799 140.356,146.799 ; 140.067,146.783 140.371,146.783 ; 140.067,147.088 139.833,147.088 ; 140.082,146.768 140.387,146.768 ; 140.082,147.073 139.828,147.073 ; 140.097,146.753 140.402,146.753 ; 140.112,146.738 140.417,146.738 ; 140.127,146.723 140.432,146.723 ; 140.143,146.707 140.448,146.707 ; 140.158,146.692 140.463,146.692 ; 140.173,146.677 140.478,146.677 ; 140.188,146.662 140.491,146.662 ; 140.204,146.646 140.506,146.646 ; 140.219,146.631 140.521,146.631 ; 140.234,146.616 140.536,146.616 ; 140.249,146.601 140.552,146.601 ; 140.265,146.585 140.567,146.585 ; 140.28,146.57 140.582,146.57 ; 140.295,146.555 140.597,146.555 ; 140.31,146.54 140.613,146.54 ; 140.323,146.524 140.628,146.524 ; 140.338,146.509 140.643,146.509 ; 140.354,146.494 140.658,146.494 ; 140.369,146.479 140.674,146.479 ; 140.384,146.463 140.689,146.463 ; 140.399,146.448 140.704,146.448 ; 140.415,146.433 140.719,146.433 ; 140.43,146.418 140.735,146.418 ; 140.445,146.402 140.75,146.402 ; 140.46,146.387 140.765,146.387 ; 140.475,146.372 140.78,146.372 ; 140.491,146.357 140.796,146.357 ; 140.506,146.342 140.811,146.342 ; 140.521,146.326 140.826,146.326 ; 140.536,146.311 140.841,146.311 ; 140.552,146.296 140.856,146.296 ; 140.567,146.281 140.872,146.281 ; 140.582,146.265 140.887,146.265 ; 140.597,146.25 140.902,146.25 ; 140.613,146.235 140.917,146.235 ; 140.628,146.22 140.933,146.22 ; 140.643,146.204 140.948,146.204 ; 140.658,146.189 140.956,146.189 ; 140.674,146.174 140.961,146.174 ; 140.689,146.159 140.963,146.159 ; 140.704,146.143 140.963,146.143 ; 140.719,146.128 140.958,146.128 ; 140.735,146.113 140.95,146.113 ; 140.75,146.098 140.94,146.098 ; 140.765,146.082 140.925,146.082 ; 140.78,146.067 140.91,146.067 ; 140.889,146.052 140.796,146.052 ; 139.828,147.073 139.833,147.088 ; 139.828,147.073 139.825,147.055 139.833,147.022 139.84,147.01 140.783,146.062 140.796,146.052 ; 139.833,147.088 139.853,147.119 ; 139.853,147.119 139.881,147.147 139.912,147.167 139.927,147.172 139.945,147.175 139.978,147.167 139.993,147.159 140.006,147.149 ; 140.006,147.149 140.948,146.202 140.956,146.189 ; 140.796,146.052 140.811,146.044 140.844,146.037 140.862,146.039 140.877,146.044 140.907,146.065 140.935,146.093 140.956,146.123 140.961,146.138 140.963,146.156 140.956,146.189
  Top Layer w0.241: 140.394,146.606 143.056,143.944 157.755,143.944 158.39,143.309
  Top Layer w0.635: 158.39,143.309 162.327,139.372 pad.1@162.327,137.086
$Net86: pad.1@164.867,137.086 | length 53.5
  Top Layer w0.03: 140.181,147.411 140.45,147.411 ; 140.183,147.396 140.465,147.396 ; 140.186,147.38 140.481,147.38 ; 140.194,147.365 140.496,147.365 ; 140.196,147.457 140.404,147.457 ; 140.206,147.35 140.511,147.35 ; 140.221,147.335 140.526,147.335 ; 140.221,147.487 140.374,147.487 ; 140.237,147.319 140.542,147.319 ; 140.239,147.502 140.359,147.502 ; 140.252,147.304 140.557,147.304 ; 140.262,147.518 140.336,147.518 ; 140.267,147.289 140.572,147.289 ; 140.282,147.274 140.587,147.274 ; 140.298,147.258 140.602,147.258 ; 140.313,147.243 140.618,147.243 ; 140.328,147.228 140.633,147.228 ; 140.343,147.213 140.648,147.213 ; 140.359,147.197 140.663,147.197 ; 140.374,147.182 140.679,147.182 ; 140.389,147.167 140.694,147.167 ; 140.389,147.472 140.206,147.472 ; 140.404,147.152 140.709,147.152 ; 140.42,147.137 140.724,147.137 ; 140.42,147.441 140.186,147.441 ; 140.435,147.121 140.74,147.121 ; 140.435,147.426 140.181,147.426 ; 140.45,147.106 140.755,147.106 ; 140.465,147.091 140.77,147.091 ; 140.481,147.076 140.785,147.076 ; 140.496,147.06 140.801,147.06 ; 140.511,147.045 140.816,147.045 ; 140.526,147.03 140.831,147.03 ; 140.542,147.015 140.844,147.015 ; 140.557,146.999 140.859,146.999 ; 140.572,146.984 140.874,146.984 ; 140.587,146.969 140.889,146.969 ; 140.602,146.954 140.905,146.954 ; 140.618,146.938 140.92,146.938 ; 140.633,146.923 140.935,146.923 ; 140.648,146.908 140.95,146.908 ; 140.663,146.893 140.966,146.893 ; 140.676,146.877 140.981,146.877 ; 140.691,146.862 140.996,146.862 ; 140.707,146.847 141.011,146.847 ; 140.722,146.832 141.027,146.832 ; 140.737,146.816 141.042,146.816 ; 140.752,146.801 141.057,146.801 ; 140.768,146.786 141.072,146.786 ; 140.783,146.771 141.088,146.771 ; 140.798,146.756 141.103,146.756 ; 140.813,146.74 141.118,146.74 ; 140.829,146.725 141.133,146.725 ; 140.844,146.71 141.149,146.71 ; 140.859,146.695 141.164,146.695 ; 140.874,146.679 141.179,146.679 ; 140.889,146.664 141.194,146.664 ; 140.905,146.649 141.21,146.649 ; 140.92,146.634 141.225,146.634 ; 140.935,146.618 141.24,146.618 ; 140.95,146.603 141.255,146.603 ; 140.966,146.588 141.27,146.588 ; 140.981,146.573 141.286,146.573 ; 140.996,146.557 141.301,146.557 ; 141.011,146.542 141.309,146.542 ; 141.027,146.527 141.314,146.527 ; 141.042,146.512 141.316,146.512 ; 141.057,146.496 141.316,146.496 ; 141.072,146.481 141.311,146.481 ; 141.088,146.466 141.304,146.466 ; 141.103,146.451 141.293,146.451 ; 141.118,146.435 141.278,146.435 ; 141.133,146.42 141.263,146.42 ; 141.243,146.405 141.149,146.405 ; 140.181,147.426 140.186,147.441 ; 140.181,147.426 140.178,147.408 140.186,147.375 140.194,147.363 141.136,146.415 141.149,146.405 ; 140.186,147.441 140.206,147.472 ; 140.206,147.472 140.234,147.5 140.265,147.52 140.28,147.525 140.298,147.528 140.331,147.52 140.346,147.512 140.359,147.502 ; 140.359,147.502 141.301,146.555 141.309,146.542 ; 141.149,146.405 141.164,146.397 141.197,146.39 141.215,146.392 141.23,146.397 141.26,146.418 141.288,146.446 141.309,146.476 141.314,146.491 141.316,146.509 141.309,146.542
  Top Layer w0.241: 140.747,146.959 143.254,144.452 159.787,144.452 160.422,143.817
  Top Layer w0.635: 160.422,143.817 164.867,139.372 pad.1@164.867,137.086
$Net87: pad.1@167.407,137.086 | length 55.8
  Top Layer w0.03: 140.534,147.764 140.803,147.764 ; 140.536,147.749 140.818,147.749 ; 140.539,147.733 140.834,147.733 ; 140.547,147.718 140.849,147.718 ; 140.549,147.81 140.757,147.81 ; 140.559,147.703 140.864,147.703 ; 140.575,147.688 140.879,147.688 ; 140.575,147.84 140.727,147.84 ; 140.59,147.672 140.895,147.672 ; 140.592,147.855 140.712,147.855 ; 140.605,147.657 140.91,147.657 ; 140.615,147.871 140.689,147.871 ; 140.62,147.642 140.925,147.642 ; 140.635,147.627 140.94,147.627 ; 140.651,147.612 140.956,147.612 ; 140.666,147.596 140.971,147.596 ; 140.681,147.581 140.986,147.581 ; 140.696,147.566 141.001,147.566 ; 140.712,147.551 141.016,147.551 ; 140.727,147.535 141.032,147.535 ; 140.742,147.52 141.047,147.52 ; 140.742,147.825 140.559,147.825 ; 140.757,147.505 141.062,147.505 ; 140.773,147.49 141.077,147.49 ; 140.773,147.794 140.539,147.794 ; 140.788,147.474 141.093,147.474 ; 140.788,147.779 140.534,147.779 ; 140.803,147.459 141.108,147.459 ; 140.818,147.444 141.123,147.444 ; 140.834,147.429 141.138,147.429 ; 140.849,147.413 141.154,147.413 ; 140.864,147.398 141.169,147.398 ; 140.879,147.383 141.184,147.383 ; 140.895,147.368 141.197,147.368 ; 140.91,147.352 141.212,147.352 ; 140.925,147.337 141.227,147.337 ; 140.94,147.322 141.243,147.322 ; 140.956,147.307 141.258,147.307 ; 140.971,147.291 141.273,147.291 ; 140.986,147.276 141.288,147.276 ; 141.001,147.261 141.304,147.261 ; 141.016,147.246 141.319,147.246 ; 141.029,147.231 141.334,147.231 ; 141.044,147.215 141.349,147.215 ; 141.06,147.2 141.364,147.2 ; 141.075,147.185 141.38,147.185 ; 141.09,147.17 141.395,147.17 ; 141.105,147.154 141.41,147.154 ; 141.121,147.139 141.425,147.139 ; 141.136,147.124 141.441,147.124 ; 141.151,147.109 141.456,147.109 ; 141.166,147.093 141.471,147.093 ; 141.182,147.078 141.486,147.078 ; 141.197,147.063 141.502,147.063 ; 141.212,147.048 141.517,147.048 ; 141.227,147.032 141.532,147.032 ; 141.243,147.017 141.547,147.017 ; 141.258,147.002 141.563,147.002 ; 141.273,146.987 141.578,146.987 ; 141.288,146.971 141.593,146.971 ; 141.304,146.956 141.608,146.956 ; 141.319,146.941 141.624,146.941 ; 141.334,146.926 141.639,146.926 ; 141.349,146.91 141.654,146.91 ; 141.364,146.895 141.662,146.895 ; 141.38,146.88 141.667,146.88 ; 141.395,146.865 141.669,146.865 ; 141.41,146.85 141.669,146.85 ; 141.425,146.834 141.664,146.834 ; 141.441,146.819 141.657,146.819 ; 141.456,146.804 141.646,146.804 ; 141.471,146.789 141.631,146.789 ; 141.486,146.773 141.616,146.773 ; 141.596,146.758 141.502,146.758 ; 140.534,147.779 140.539,147.794 ; 140.534,147.779 140.531,147.761 140.539,147.728 140.547,147.716 141.489,146.768 141.502,146.758 ; 140.539,147.794 140.559,147.825 ; 140.559,147.825 140.587,147.853 140.618,147.873 140.633,147.878 140.651,147.881 140.684,147.873 140.699,147.866 140.712,147.855 ; 140.712,147.855 141.654,146.908 141.662,146.895 ; 141.502,146.758 141.517,146.75 141.55,146.743 141.568,146.745 141.583,146.75 141.613,146.771 141.641,146.799 141.662,146.829 141.667,146.844 141.669,146.862 141.662,146.895
  Top Layer w0.241: 141.1,147.312 143.455,144.96 161.819,144.96 162.454,144.325
  Top Layer w0.635: 162.454,144.325 167.407,139.372 pad.1@167.407,137.086
$Net88: pad.1@169.947,137.086 | length 58.1
  Top Layer w0.03: 140.887,148.117 141.156,148.117 ; 140.889,148.102 141.171,148.102 ; 140.892,148.086 141.187,148.086 ; 140.9,148.071 141.202,148.071 ; 140.902,148.163 141.11,148.163 ; 140.912,148.056 141.217,148.056 ; 140.928,148.041 141.232,148.041 ; 140.928,148.193 141.08,148.193 ; 140.943,148.026 141.248,148.026 ; 140.945,148.208 141.065,148.208 ; 140.958,148.01 141.263,148.01 ; 140.968,148.224 141.042,148.224 ; 140.973,147.995 141.278,147.995 ; 140.989,147.98 141.293,147.98 ; 141.004,147.965 141.309,147.965 ; 141.019,147.949 141.324,147.949 ; 141.034,147.934 141.339,147.934 ; 141.05,147.919 141.354,147.919 ; 141.065,147.904 141.37,147.904 ; 141.08,147.888 141.385,147.888 ; 141.095,147.873 141.4,147.873 ; 141.095,148.178 140.912,148.178 ; 141.11,147.858 141.415,147.858 ; 141.126,147.843 141.431,147.843 ; 141.126,148.147 140.892,148.147 ; 141.141,147.827 141.446,147.827 ; 141.141,148.132 140.887,148.132 ; 141.156,147.812 141.461,147.812 ; 141.171,147.797 141.476,147.797 ; 141.187,147.782 141.491,147.782 ; 141.202,147.766 141.507,147.766 ; 141.217,147.751 141.522,147.751 ; 141.232,147.736 141.537,147.736 ; 141.248,147.721 141.55,147.721 ; 141.263,147.705 141.565,147.705 ; 141.278,147.69 141.58,147.69 ; 141.293,147.675 141.596,147.675 ; 141.309,147.66 141.611,147.66 ; 141.324,147.645 141.626,147.645 ; 141.339,147.629 141.641,147.629 ; 141.354,147.614 141.657,147.614 ; 141.37,147.599 141.672,147.599 ; 141.382,147.584 141.687,147.584 ; 141.397,147.568 141.702,147.568 ; 141.413,147.553 141.718,147.553 ; 141.428,147.538 141.733,147.538 ; 141.443,147.523 141.748,147.523 ; 141.458,147.507 141.763,147.507 ; 141.474,147.492 141.778,147.492 ; 141.489,147.477 141.794,147.477 ; 141.504,147.462 141.809,147.462 ; 141.519,147.446 141.824,147.446 ; 141.535,147.431 141.839,147.431 ; 141.55,147.416 141.855,147.416 ; 141.565,147.401 141.87,147.401 ; 141.58,147.385 141.885,147.385 ; 141.596,147.37 141.9,147.37 ; 141.611,147.355 141.916,147.355 ; 141.626,147.34 141.931,147.34 ; 141.641,147.324 141.946,147.324 ; 141.657,147.309 141.961,147.309 ; 141.672,147.294 141.977,147.294 ; 141.687,147.279 141.992,147.279 ; 141.702,147.264 142.007,147.264 ; 141.718,147.248 142.015,147.248 ; 141.733,147.233 142.02,147.233 ; 141.748,147.218 142.022,147.218 ; 141.763,147.203 142.022,147.203 ; 141.778,147.187 142.017,147.187 ; 141.794,147.172 142.01,147.172 ; 141.809,147.157 141.999,147.157 ; 141.824,147.142 141.984,147.142 ; 141.839,147.126 141.969,147.126 ; 141.949,147.111 141.855,147.111 ; 140.887,148.132 140.892,148.147 ; 140.887,148.132 140.884,148.114 140.892,148.081 140.9,148.069 141.842,147.121 141.855,147.111 ; 140.892,148.147 140.912,148.178 ; 140.912,148.178 140.94,148.206 140.971,148.226 140.986,148.231 141.004,148.234 141.037,148.226 141.052,148.219 141.065,148.208 ; 141.065,148.208 142.007,147.261 142.015,147.248 ; 141.855,147.111 141.87,147.104 141.903,147.096 141.921,147.098 141.936,147.104 141.966,147.124 141.994,147.152 142.015,147.182 142.02,147.197 142.022,147.215 142.015,147.248
  Top Layer w0.241: 141.453,147.665 143.653,145.468 163.851,145.468 164.486,144.833
  Top Layer w0.635: 164.486,144.833 169.947,139.372 pad.1@169.947,137.086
